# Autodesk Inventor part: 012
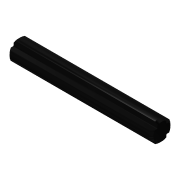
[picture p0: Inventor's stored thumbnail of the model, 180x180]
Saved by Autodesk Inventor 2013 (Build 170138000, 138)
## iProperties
Created: 2013-02
Part Number: 012
Material: Generic
Document SubType Name: Modeling
Designer: perblt
Density: 1 g/cm^3
Author: perblt
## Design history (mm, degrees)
sketch "Sketch1"
  geometry: L1 (1, -2.182)-(-1, -2.182); L2 (-1, 2.182)-(1, 2.182); L3 (1, -2.182)-(-1, 2.182); L4 (-1, -2.182)-(1, 2.182); L5 (-2.182, -1)-(-2.182, 1); L6 (2.182, 1)-(2.182, -1); L7 (2.182, -1)-(-2.182, 1); L8 (-2.182, -1)-(2.182, 1); L9 (2.182, -1)-(1, -1); L10 (-1, -1)-(-2.182, -1); L11 (1, 2.182)-(1, 1); L12 (1, -1)-(1, -2.182); L13 (-2.182, 1)-(-1, 1); L14 (1, 1)-(2.182, 1); L15 (-1, -2.182)-(-1, -1); L16 (-1, 1)-(-1, 2.182); A1 r 2.4 centre (0, 0) between (-1, -2.182) and (1, -2.182); A2 r 2.4 centre (0, 0) between (2.182, -1) and (2.182, 1); A3 r 2.4 centre (0, 0) between (1, 2.182) and (-1, 2.182); A4 r 2.4 centre (0, 0) between (-2.182, 1) and (-2.182, -1); 1 further point
  constraints: 32 end point, 10 parallel, 8 point on circle, 4 centre point, 4 midpoint, 4 perpendicular, 3 horizontal, 1 coincident
  dimensions: "d1" = 2 distance of L2.start L2.end; "d2" = 2 distance of L5.start L5.end
extrude "Extrusion1" new body sketch "Sketch1" distance "d3" = 32; taper "d4" = 0 deg
chamfer "Chamfer1" distance "d5" = 0.5; stored, may be unused: second distance "d6" = 2, angle "d7" = 45 deg
chamfer "Chamfer2" distance "d8" = 0.5; stored, may be unused: second distance "d9" = 2, angle "d10" = 45 deg
chamfer "Chamfer3" distance "d11" = 0.1; stored, may be unused: second distance "d12" = 2, angle "d13" = 45 deg
body "Solid1"
other parameters: "d0" = 4.8
